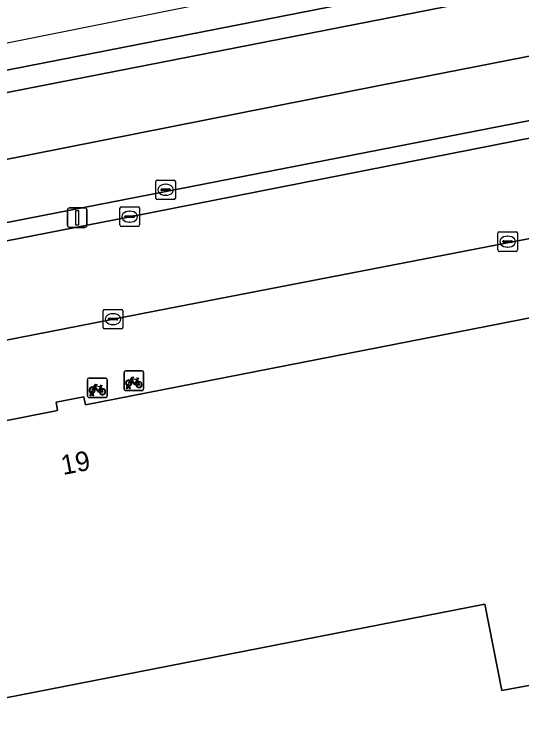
# Model space of a CAD drawing. Extents: x 160377 to 161131, y 383938 to 384853.
# Drawn here: x 160704.85 to 160730.83, y 384786.44 to 384822.34 of the extents above; entities that cross this region are included whole.
import ezdxf

# ---------------------------------------------------------------- set-up
doc = ezdxf.new("R2010")
doc.units = 0
for name, color, linetype in [('IMGEO_Berm_open', 7, 'Continuous'), ('IMGEO_Erf', 7, 'Continuous'), ('IMGEO_Fietsenrek', 7, 'Continuous'), ('IMGEO_Kolk', 7, 'Continuous'), ('IMGEO_Lichtmast', 7, 'Continuous'), ('IMGEO_Pand', 7, 'Continuous'), ('IMGEO_Pand_nummerreeks', 7, 'Continuous'), ('IMGEO_Rijbaan_lokaal_open', 7, 'Continuous'), ('IMGEO_Rijbaan_regionaal_gesloten', 7, 'Continuous'), ('IMGEO_Verkeerseiland_open', 7, 'Continuous'), ('IMGEO_Voetpad_open', 7, 'Continuous')]:
    doc.layers.add(name, color=color, linetype=linetype)

msp = doc.modelspace()

# ---------------------------------------------------------------- linework, layer by layer
at = {"layer": 'IMGEO_Berm_open'}
for points in [[(160753.962, 384821.317), (160669.687, 384804.898)], [(160668.863, 384803.782), (160690.315, 384807.978), (160710.765, 384811.973), (160731.557, 384816.055), (160751.991, 384820.036), (160754.132, 384820.304)]]:
    msp.add_lwpolyline(points, dxfattribs=at)
at = {"layer": 'IMGEO_Erf'}
msp.add_lwpolyline([(160741.415, 384766.337), (160739.423, 384776.849), (160733.726, 384775.784), (160732.21, 384783.572), (160738.052, 384784.675), (160737.348, 384789.133), (160729.789, 384787.742), (160728.933, 384792.151), (160683.571, 384783.298)], dxfattribs=at)
at = {"layer": 'IMGEO_Fietsenrek'}
for p, q in [((160710.472, 384803.16), (160710.472, 384804.001)), ((160710.472, 384804.001), (160710.472, 384803.16)), ((160710.547, 384804.085), (160711.388, 384804.085)), ((160711.388, 384804.085), (160710.547, 384804.085)), ((160711.472, 384804.01), (160711.472, 384803.169)), ((160711.472, 384803.169), (160711.472, 384804.01)), ((160708.607, 384802.796), (160708.607, 384803.637)), ((160708.607, 384803.637), (160708.607, 384802.796)), ((160708.682, 384803.721), (160709.523, 384803.721)), ((160709.523, 384803.721), (160708.682, 384803.721)), ((160709.607, 384803.646), (160709.607, 384802.805)), ((160709.607, 384802.805), (160709.607, 384803.646)), ((160711.159, 384803.634), (160711.195, 384803.539)), ((160709.294, 384803.27), (160709.33, 384803.175)), ((160710.599, 384803.169), (160710.638, 384803.329)), ((160710.668, 384803.317), (160710.633, 384803.169)), ((160710.71, 384803.341), (160710.709, 384803.345)), ((160710.751, 384803.169), (160710.717, 384803.311)), ((160710.741, 384803.352), (160710.742, 384803.345)), ((160710.749, 384803.315), (160710.784, 384803.169)), ((160708.734, 384802.805), (160708.773, 384802.965)), ((160708.803, 384802.953), (160708.768, 384802.805)), ((160708.845, 384802.977), (160708.844, 384802.981)), ((160708.886, 384802.805), (160708.852, 384802.947)), ((160708.876, 384802.988), (160708.877, 384802.981)), ((160708.884, 384802.951), (160708.919, 384802.805)), ((160711.397, 384803.085), (160710.556, 384803.085)), ((160710.556, 384803.085), (160711.397, 384803.085)), ((160710.633, 384803.169), (160710.599, 384803.169)), ((160710.784, 384803.169), (160710.751, 384803.169)), ((160709.532, 384802.721), (160708.691, 384802.721)), ((160708.691, 384802.721), (160709.532, 384802.721)), ((160708.768, 384802.805), (160708.734, 384802.805)), ((160708.919, 384802.805), (160708.886, 384802.805))]:
    msp.add_line(p, q, dxfattribs=at)
for points in [[(160710.785, 384803.611), (160710.88, 384803.775), (160710.966, 384803.761), (160710.968, 384803.752), (160710.912, 384803.741), (160710.885, 384803.696), (160711.141, 384803.655)], [(160711.128, 384803.63), (160710.871, 384803.671), (160710.854, 384803.642), (160711.021, 384803.422), (160711.128, 384803.63)], [(160711.141, 384803.655), (160711.166, 384803.704), (160711.16, 384803.708), (160711.137, 384803.712), (160711.125, 384803.719), (160711.124, 384803.722), (160711.126, 384803.727), (160711.221, 384803.712), (160711.223, 384803.702), (160711.213, 384803.689), (160711.201, 384803.683), (160711.187, 384803.689), (160711.159, 384803.634)], [(160708.92, 384803.247), (160709.015, 384803.411), (160709.101, 384803.397), (160709.103, 384803.388), (160709.047, 384803.377), (160709.02, 384803.332), (160709.276, 384803.291)], [(160709.263, 384803.266), (160709.006, 384803.307), (160708.989, 384803.278), (160709.156, 384803.058), (160709.263, 384803.266)], [(160709.276, 384803.291), (160709.301, 384803.34), (160709.295, 384803.344), (160709.272, 384803.348), (160709.26, 384803.355), (160709.259, 384803.358), (160709.261, 384803.363), (160709.356, 384803.348), (160709.358, 384803.338), (160709.348, 384803.325), (160709.336, 384803.319), (160709.322, 384803.325), (160709.294, 384803.27)], [(160710.806, 384803.559), (160710.754, 384803.469), (160710.714, 384803.444), (160710.715, 384803.491), (160710.77, 384803.585)], [(160711.081, 384803.367), (160711.031, 384803.367), (160710.84, 384803.618), (160710.821, 384803.586)], [(160711.176, 384803.532), (160711.146, 384803.609), (160711.037, 384803.391), (160711.08, 384803.391)], [(160711.11, 384803.391), (160711.23, 384803.39), (160711.186, 384803.504)], [(160711.206, 384803.511), (160711.261, 384803.366), (160711.111, 384803.366)], [(160708.941, 384803.195), (160708.889, 384803.105), (160708.849, 384803.08), (160708.85, 384803.127), (160708.905, 384803.221)], [(160709.216, 384803.003), (160709.166, 384803.003), (160708.975, 384803.254), (160708.956, 384803.222)], [(160709.311, 384803.168), (160709.281, 384803.245), (160709.172, 384803.027), (160709.215, 384803.027)], [(160709.245, 384803.027), (160709.365, 384803.026), (160709.321, 384803.14)], [(160709.341, 384803.147), (160709.396, 384803.002), (160709.246, 384803.002)]]:
    msp.add_lwpolyline(points, dxfattribs=at)
for centre, radius, start, end in [((160710.55, 384804.007), 0.0779, 92.4484, 184.2845), ((160710.55, 384804.007), 0.0779, 92.4484, 184.2845), ((160711.394, 384804.007), 0.0779, 2.4484, 94.2845), ((160711.394, 384804.007), 0.0779, 2.4484, 94.2845), ((160708.685, 384803.643), 0.0779, 92.4484, 184.2845), ((160708.685, 384803.643), 0.0779, 92.4484, 184.2845), ((160709.529, 384803.643), 0.0779, 2.4484, 94.2845), ((160709.529, 384803.643), 0.0779, 2.4484, 94.2845), ((160710.712, 384803.47), 0.159, 62.6766, 242.1369), ((160708.847, 384803.106), 0.159, 62.6766, 242.1369), ((160710.712, 384803.47), 0.129, 63.3192, 238.903), ((160710.692, 384803.341), 0.0499, 12.8025, 158.6934), ((160710.712, 384803.47), 0.159, 253.9967, 271.7867), ((160710.692, 384803.341), 0.0174, 12.8025, 163.4502), ((160710.712, 384803.47), 0.129, 253.415, 269.0204), ((160710.712, 384803.47), 0.129, 283.6043, 43.4302), ((160710.712, 384803.47), 0.159, 283.5766, 46.6042), ((160711.239, 384803.386), 0.159, 113.3408, 178.3217), ((160711.239, 384803.386), 0.159, 187.0065, 105.7708), ((160711.239, 384803.386), 0.129, 113.923, 177.9556), ((160711.239, 384803.386), 0.129, 188.6715, 104.5883), ((160708.847, 384803.106), 0.129, 63.3192, 238.903), ((160708.827, 384802.977), 0.0499, 12.8025, 158.6934), ((160708.847, 384803.106), 0.159, 253.9967, 271.7867), ((160708.827, 384802.977), 0.0174, 12.8025, 163.4502), ((160708.847, 384803.106), 0.129, 253.415, 269.0204), ((160708.847, 384803.106), 0.129, 283.6043, 43.4302), ((160708.847, 384803.106), 0.159, 283.5766, 46.6042), ((160709.374, 384803.022), 0.159, 113.3408, 178.3217), ((160709.374, 384803.022), 0.159, 187.0065, 105.7708), ((160709.374, 384803.022), 0.129, 113.923, 177.9556), ((160709.374, 384803.022), 0.129, 188.6715, 104.5883), ((160710.55, 384803.163), 0.0779, 182.4484, 274.2845), ((160710.55, 384803.163), 0.0779, 182.4484, 274.2845), ((160711.394, 384803.163), 0.0779, 272.4484, 4.2845), ((160711.394, 384803.163), 0.0779, 272.4484, 4.2845), ((160708.685, 384802.799), 0.0779, 182.4484, 274.2845), ((160708.685, 384802.799), 0.0779, 182.4484, 274.2845), ((160709.529, 384802.799), 0.0779, 272.4484, 4.2845), ((160709.529, 384802.799), 0.0779, 272.4484, 4.2845)]:
    msp.add_arc(centre, radius, start, end, dxfattribs=at)
at = {"layer": 'IMGEO_Kolk'}
for p, q in [((160712.1, 384812.923), (160712.1, 384813.775)), ((160712.175, 384813.849), (160713.027, 384813.849)), ((160713.101, 384813.775), (160713.101, 384812.923)), ((160712.359, 384813.343), (160712.359, 384813.355)), ((160712.402, 384813.392), (160712.8, 384813.392)), ((160712.588, 384813.629), (160712.613, 384813.629)), ((160712.843, 384813.355), (160712.843, 384813.343)), ((160712.797, 384813.306), (160712.399, 384813.306)), ((160712.611, 384813.069), (160712.586, 384813.069)), ((160713.027, 384812.849), (160712.175, 384812.849)), ((160710.264, 384811.549), (160710.264, 384812.401)), ((160710.339, 384812.475), (160711.191, 384812.475)), ((160710.752, 384812.255), (160710.777, 384812.255)), ((160711.265, 384812.401), (160711.265, 384811.549)), ((160710.523, 384811.969), (160710.523, 384811.981)), ((160710.961, 384811.932), (160710.563, 384811.932)), ((160710.566, 384812.018), (160710.964, 384812.018)), ((160711.007, 384811.981), (160711.007, 384811.969)), ((160710.775, 384811.695), (160710.75, 384811.695)), ((160711.191, 384811.475), (160710.339, 384811.475)), ((160729.669, 384811.197), (160730.521, 384811.197)), ((160729.594, 384810.271), (160729.594, 384811.123)), ((160730.082, 384810.977), (160730.107, 384810.977)), ((160730.595, 384811.123), (160730.595, 384810.271)), ((160729.853, 384810.691), (160729.853, 384810.703)), ((160730.291, 384810.654), (160729.893, 384810.654)), ((160729.896, 384810.74), (160730.294, 384810.74)), ((160730.337, 384810.703), (160730.337, 384810.691)), ((160730.521, 384810.197), (160729.669, 384810.197)), ((160730.105, 384810.417), (160730.08, 384810.417)), ((160709.483, 384807.234), (160710.335, 384807.234)), ((160709.408, 384806.308), (160709.408, 384807.16)), ((160709.896, 384807.014), (160709.921, 384807.014)), ((160710.409, 384807.16), (160710.409, 384806.308)), ((160709.667, 384806.728), (160709.667, 384806.74)), ((160710.105, 384806.691), (160709.707, 384806.691)), ((160709.71, 384806.777), (160710.108, 384806.777)), ((160710.151, 384806.74), (160710.151, 384806.728)), ((160710.335, 384806.234), (160709.483, 384806.234)), ((160709.919, 384806.454), (160709.894, 384806.454))]:
    msp.add_line(p, q, dxfattribs=at)
for points in [[(160712.1, 384812.923), (160712.1, 384813.775)], [(160712.175, 384813.849), (160713.027, 384813.849)], [(160713.101, 384813.775), (160713.101, 384812.923)], [(160713.027, 384812.849), (160712.175, 384812.849)], [(160710.264, 384811.549), (160710.264, 384812.401)], [(160710.339, 384812.475), (160711.191, 384812.475)], [(160711.265, 384812.401), (160711.265, 384811.549)], [(160711.191, 384811.475), (160710.339, 384811.475)], [(160729.669, 384811.197), (160730.521, 384811.197)], [(160729.594, 384810.271), (160729.594, 384811.123)], [(160730.595, 384811.123), (160730.595, 384810.271)], [(160730.521, 384810.197), (160729.669, 384810.197)], [(160709.483, 384807.234), (160710.335, 384807.234)], [(160709.408, 384806.308), (160709.408, 384807.16)], [(160710.409, 384807.16), (160710.409, 384806.308)], [(160710.335, 384806.234), (160709.483, 384806.234)]]:
    msp.add_lwpolyline(points, dxfattribs=at)
for centre, radius, start, end in [((160712.177, 384813.773), 0.0765, 91.552, 178.448), ((160712.177, 384813.773), 0.0765, 91.552, 178.448), ((160713.025, 384813.773), 0.0765, 1.552, 88.448), ((160713.025, 384813.773), 0.0765, 1.552, 88.448), ((160712.399, 384813.352), 0.0403, 85.8775, 175.7526), ((160712.396, 384813.342), 0.0366, 178.938, 274.7102), ((160712.8, 384813.349), 0.043, 264.8664, 352.4533), ((160712.804, 384813.354), 0.0386, 1.7309, 96.639), ((160712.177, 384812.925), 0.0765, 181.552, 268.448), ((160712.177, 384812.925), 0.0765, 181.552, 268.448), ((160713.025, 384812.925), 0.0765, 271.552, 358.448), ((160713.025, 384812.925), 0.0765, 271.552, 358.448), ((160710.341, 384812.399), 0.0765, 91.552, 178.448), ((160710.341, 384812.399), 0.0765, 91.552, 178.448), ((160711.189, 384812.399), 0.0765, 1.552, 88.448), ((160711.189, 384812.399), 0.0765, 1.552, 88.448), ((160710.563, 384811.978), 0.0403, 85.8775, 175.7526), ((160710.56, 384811.968), 0.0366, 178.938, 274.7102), ((160710.964, 384811.975), 0.043, 264.8664, 352.4533), ((160710.968, 384811.98), 0.0386, 1.7309, 96.639), ((160710.341, 384811.551), 0.0765, 181.552, 268.448), ((160710.341, 384811.551), 0.0765, 181.552, 268.448), ((160711.189, 384811.551), 0.0765, 271.552, 358.448), ((160711.189, 384811.551), 0.0765, 271.552, 358.448), ((160729.671, 384811.121), 0.0765, 91.552, 178.448), ((160729.671, 384811.121), 0.0765, 91.552, 178.448), ((160730.519, 384811.121), 0.0765, 1.552, 88.448), ((160730.519, 384811.121), 0.0765, 1.552, 88.448), ((160729.893, 384810.7), 0.0403, 85.8775, 175.7526), ((160729.89, 384810.69), 0.0366, 178.938, 274.7102), ((160730.294, 384810.697), 0.043, 264.8664, 352.4533), ((160730.298, 384810.702), 0.0386, 1.7309, 96.639), ((160729.671, 384810.273), 0.0765, 181.552, 268.448), ((160729.671, 384810.273), 0.0765, 181.552, 268.448), ((160730.519, 384810.273), 0.0765, 271.552, 358.448), ((160730.519, 384810.273), 0.0765, 271.552, 358.448), ((160709.485, 384807.158), 0.0765, 91.552, 178.448), ((160709.485, 384807.158), 0.0765, 91.552, 178.448), ((160710.333, 384807.158), 0.0765, 1.552, 88.448), ((160710.333, 384807.158), 0.0765, 1.552, 88.448), ((160709.707, 384806.737), 0.0403, 85.8775, 175.7526), ((160709.704, 384806.727), 0.0366, 178.938, 274.7102), ((160710.108, 384806.734), 0.043, 264.8664, 352.4533), ((160710.112, 384806.739), 0.0386, 1.7309, 96.639), ((160709.485, 384806.31), 0.0765, 181.552, 268.448), ((160709.485, 384806.31), 0.0765, 181.552, 268.448), ((160710.333, 384806.31), 0.0765, 271.552, 358.448), ((160710.333, 384806.31), 0.0765, 271.552, 358.448)]:
    msp.add_arc(centre, radius, start, end, dxfattribs=at)
for centre, major_axis, ratio, start_param, end_param in [((160712.587, 384813.349), (-0.387, 0.002), 0.722429, 4.712389, 7.853982), ((160712.612, 384813.349), (-0.39, 0.002), 0.717154, 1.570796, 4.712389), ((160710.751, 384811.975), (-0.387, 0.002), 0.722429, 4.712389, 7.853982), ((160710.776, 384811.975), (-0.39, 0.002), 0.717154, 1.570796, 4.712389), ((160730.081, 384810.697), (-0.387, 0.002), 0.722429, 4.712389, 7.853982), ((160730.106, 384810.697), (-0.39, 0.002), 0.717154, 1.570796, 4.712389), ((160709.895, 384806.734), (-0.387, 0.002), 0.722429, 4.712389, 7.853982), ((160709.92, 384806.734), (-0.39, 0.002), 0.717154, 1.570796, 4.712389)]:
    msp.add_ellipse(centre, major_axis=major_axis, ratio=ratio, start_param=start_param, end_param=end_param, dxfattribs=at)
at = {"layer": 'IMGEO_Lichtmast'}
for p, q in [((160707.581, 384811.523), (160707.581, 384812.323)), ((160707.581, 384812.323), (160707.581, 384811.523)), ((160707.681, 384812.423), (160708.471, 384812.423)), ((160708.471, 384812.423), (160707.681, 384812.423)), ((160708.571, 384812.323), (160708.571, 384811.523)), ((160708.571, 384811.523), (160708.571, 384812.323)), ((160708.471, 384811.423), (160707.681, 384811.423)), ((160707.681, 384811.423), (160708.471, 384811.423))]:
    msp.add_line(p, q, dxfattribs=at)
msp.add_lwpolyline([(160708.001, 384812.298), (160708.151, 384812.298), (160708.151, 384811.548), (160708.001, 384811.548), (160708.001, 384812.298)], dxfattribs=at)
for centre, start, end in [((160707.681, 384812.323), 90, 180), ((160707.681, 384812.323), 90, 180), ((160708.471, 384812.323), 0, 90), ((160708.471, 384812.323), 360, 90), ((160707.681, 384811.523), 180, 270), ((160707.681, 384811.523), 180, 270), ((160708.471, 384811.523), 270, 0), ((160708.471, 384811.523), 270, 0)]:
    msp.add_arc(centre, 0.1, start, end, dxfattribs=at)
at = {"layer": 'IMGEO_Pand'}
msp.add_lwpolyline([(160734.212, 384805.42), (160733.849, 384807.308), (160708.498, 384802.355), (160708.412, 384802.765), (160706.995, 384802.488), (160707.079, 384802.056), (160704.115, 384801.479), (160703.994, 384801.892), (160702.589, 384801.624), (160702.668, 384801.211), (160680.864, 384796.949), (160683.571, 384783.298), (160728.933, 384792.151), (160729.789, 384787.742), (160737.348, 384789.133), (160736.294, 384794.606), (160736.096, 384795.636)], close=True, dxfattribs=at)
at = {"layer": 'IMGEO_Rijbaan_lokaal_open'}
for points in [[(160745.246, 384813.658), (160756.944, 384815.951), (160756.782, 384816.801), (160754.132, 384820.304), (160751.991, 384820.036), (160731.557, 384816.055), (160710.765, 384811.973), (160690.315, 384807.978), (160668.863, 384803.782)], [(160712.036, 384807.136), (160731.148, 384810.84), (160732.219, 384810.957)], [(160669.558, 384798.838), (160712.036, 384807.136)]]:
    msp.add_lwpolyline(points, dxfattribs=at)
at = {"layer": 'IMGEO_Rijbaan_regionaal_gesloten'}
for points in [[(160821.599, 384844.146), (160829.468, 384845.895), (160829.618, 384845.927), (160829.254, 384846.905), (160806.499, 384841.714), (160790.719, 384838.114), (160734.589, 384826.879), (160672.527, 384814.457), (160614.171, 384806.098), (160545.148, 384802.929), (160536.931, 384801.145)], [(160620.019, 384800.647), (160623.941, 384800.965), (160636.271, 384802.448), (160652.633, 384805.11), (160663.941, 384807.107), (160687.886, 384811.633), (160723.538, 384818.688), (160757.394, 384825.337), (160773.567, 384827.732), (160796.581, 384831.06), (160808.154, 384832.524), (160820.659, 384834.653), (160832.812, 384837.187), (160831.861, 384840.102), (160818.009, 384837.306), (160805.372, 384835.31), (160791.27, 384833.313), (160761.012, 384829.451), (160759.855, 384829.172), (160673.267, 384812.223)], [(160666.233, 384811.987), (160791.269, 384836.471), (160798.406, 384838.282)], [(160833.826, 384834.082), (160832.812, 384837.187), (160820.659, 384834.653), (160808.154, 384832.524), (160796.581, 384831.06), (160773.567, 384827.732), (160757.394, 384825.337), (160723.538, 384818.688), (160687.886, 384811.633), (160663.941, 384807.107), (160652.633, 384805.11), (160636.271, 384802.448), (160623.941, 384800.965), (160620.019, 384800.647)], [(160669.687, 384804.898), (160753.962, 384821.317)]]:
    msp.add_lwpolyline(points, dxfattribs=at)
at = {"layer": 'IMGEO_Verkeerseiland_open'}
msp.add_lwpolyline([(160673.267, 384812.223), (160759.855, 384829.172), (160761.012, 384829.451), (160791.519, 384835.419), (160791.269, 384836.471), (160666.233, 384811.987)], dxfattribs=at)
at = {"layer": 'IMGEO_Voetpad_open'}
for points in [[(160732.219, 384810.957), (160731.148, 384810.84), (160712.036, 384807.136), (160669.558, 384798.838)], [(160702.668, 384801.211), (160702.589, 384801.624), (160703.994, 384801.892), (160704.115, 384801.479), (160707.079, 384802.056), (160706.995, 384802.488), (160708.412, 384802.765), (160708.498, 384802.355), (160733.849, 384807.308), (160734.212, 384805.42), (160737.223, 384805.988), (160736.981, 384807.336)]]:
    msp.add_lwpolyline(points, dxfattribs=at)

# ---------------------------------------------------------------- texts
at = {"layer": 'IMGEO_Pand_nummerreeks'}
msp.add_text('19', height=1, rotation=11.018, dxfattribs=at).set_placement((160707.352, 384798.758))

doc.saveas('drawing.dxf')
